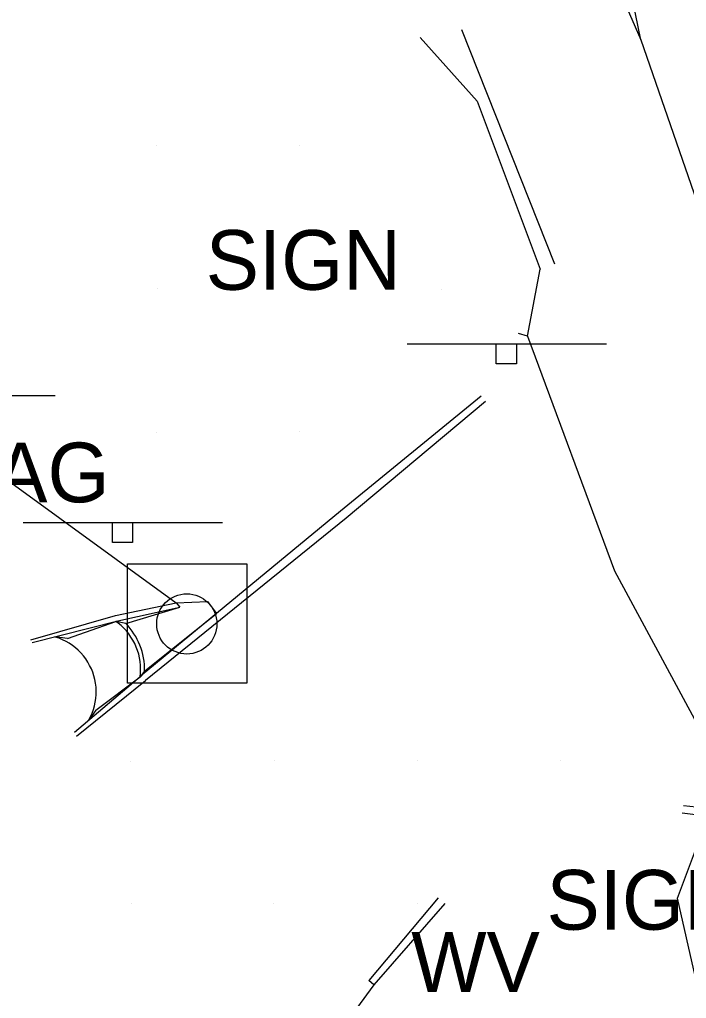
# Model space of a CAD drawing. Extents: x 1602514 to 1609837, y 863887 to 871157.
# Drawn here: x 1604808.5 to 1604878.4, y 866771.5 to 866874 of the extents above; entities that cross this region are included whole.
import ezdxf

# ---------------------------------------------------------------- set-up
doc = ezdxf.new("R2010")
doc.units = 0
for name, color, linetype in [('Roadway-Signs', 7, 'Continuous'), ('Survey-Centerline', 7, 'Continuous'), ('Survey-Curbs', 7, 'Continuous'), ('Survey-Edge of pavement', 7, 'Continuous'), ('Survey-Miscellaneous roadside', 7, 'Continuous'), ('Survey-Ridge Lines', 7, 'Continuous'), ('Survey-Shoulders', 7, 'Continuous'), ('Survey-Spot dirt', 7, 'Continuous'), ('Utility-Water', 7, 'Continuous')]:
    doc.layers.add(name, color=color, linetype=linetype)

msp = doc.modelspace()

# ---------------------------------------------------------------- linework, layer by layer
at = {"layer": 'Roadway-Signs'}
for p, q in [((1604849.12, 866840.02), (1604870.02, 866840.02)), ((1604849.12, 866840.02), (1604870.02, 866840.02)), ((1604858.47, 866837.92), (1604858.47, 866840.02)), ((1604858.47, 866837.92), (1604858.47, 866840.02)), ((1604859.52, 866840.02), (1604859.52, 866840.02)), ((1604859.52, 866840.02), (1604859.52, 866840.02)), ((1604860.57, 866840.02), (1604860.57, 866837.92)), ((1604860.57, 866840.02), (1604860.57, 866837.92)), ((1604860.57, 866837.92), (1604858.47, 866837.92)), ((1604860.57, 866837.92), (1604858.47, 866837.92)), ((1604791.37, 866834.63), (1604812.27, 866834.63)), ((1604791.37, 866834.63), (1604812.27, 866834.63)), ((1604808.91, 866821.33), (1604829.81, 866821.33)), ((1604808.91, 866821.33), (1604829.81, 866821.33)), ((1604818.26, 866819.23), (1604818.26, 866821.33)), ((1604818.26, 866819.23), (1604818.26, 866821.33)), ((1604819.31, 866821.33), (1604819.31, 866821.33)), ((1604819.31, 866821.33), (1604819.31, 866821.33)), ((1604820.36, 866821.33), (1604820.36, 866819.23)), ((1604820.36, 866821.33), (1604820.36, 866819.23)), ((1604820.36, 866819.23), (1604818.26, 866819.23)), ((1604820.36, 866819.23), (1604818.26, 866819.23))]:
    msp.add_line(p, q, dxfattribs=at)
at = {"layer": 'Survey-Centerline'}
msp.add_lwpolyline([(1604873.59, 866871.86), (1604870.26, 866888.2), (1604868.28, 866902.98), (1604861.37, 866899.9), (1604873.59, 866871.86)], dxfattribs=at)
msp.add_lwpolyline([(1604873.59, 866871.86), (1604870.26, 866888.2), (1604868.28, 866902.98), (1604861.37, 866899.9), (1604873.59, 866871.86)], dxfattribs=at)
at = {"layer": 'Survey-Curbs'}
for p, q in [((1604861.73, 866840.82), (1604860.81, 866841.1)), ((1604861.73, 866840.82), (1604860.81, 866841.1)), ((1604856.89, 866834.56), (1604842.14, 866822.52)), ((1604856.89, 866834.56), (1604842.14, 866822.52)), ((1604842.14, 866822.52), (1604821.39, 866805.36)), ((1604842.14, 866822.52), (1604821.39, 866805.36)), ((1604818.85, 866811.03), (1604825.31, 866812.46)), ((1604818.85, 866811.03), (1604825.31, 866812.46)), ((1604809.71, 866809.05), (1604818.59, 866811.58)), ((1604809.71, 866809.05), (1604818.59, 866811.58)), ((1604809.86, 866808.74), (1604818.85, 866811.03)), ((1604809.86, 866808.74), (1604818.85, 866811.03)), ((1604814.31, 866799.38), (1604821.39, 866805.36)), ((1604814.31, 866799.38), (1604821.39, 866805.36)), ((1604814.51, 866798.94), (1604821.73, 866804.77)), ((1604814.51, 866798.94), (1604821.73, 866804.77)), ((1604884.49, 866790.95), (1604878.07, 866791.65)), ((1604884.49, 866790.95), (1604878.07, 866791.65)), ((1604852.37, 866782.01), (1604845.13, 866773.36)), ((1604852.37, 866782.01), (1604845.13, 866773.36)), ((1604853.08, 866781.42), (1604845.65, 866772.91)), ((1604853.08, 866781.42), (1604845.65, 866772.91)), ((1604845.65, 866772.91), (1604845.13, 866773.36)), ((1604845.65, 866772.91), (1604845.13, 866773.36))]:
    msp.add_line(p, q, dxfattribs=at)
for points in [[(1604857.35, 866834), (1604842.76, 866821.76), (1604821.73, 866804.77)], [(1604857.35, 866834), (1604842.76, 866821.76), (1604821.73, 866804.77)], [(1604818.59, 866811.58), (1604824.93, 866812.89), (1604825.31, 866812.46)], [(1604818.59, 866811.58), (1604824.93, 866812.89), (1604825.31, 866812.46)], [(1604884.49, 866790.95), (1604884.32, 866790.1), (1604877.92, 866790.89)], [(1604884.49, 866790.95), (1604884.32, 866790.1), (1604877.92, 866790.89)]]:
    msp.add_lwpolyline(points, dxfattribs=at)
at = {"layer": 'Survey-Edge of pavement'}
for p, q in [((1604854.82, 866872.94), (1604864.57, 866848.39)), ((1604854.82, 866872.94), (1604864.57, 866848.39)), ((1604861.73, 866840.82), (1604863.05, 866847.84)), ((1604861.73, 866840.82), (1604863.05, 866847.84))]:
    msp.add_line(p, q, dxfattribs=at)
for points in [[(1604691.74, 866913.93), (1604754.93, 866864.89), (1604787.98, 866839.79), (1604824.93, 866812.89)], [(1604691.74, 866913.93), (1604754.93, 866864.89), (1604787.98, 866839.79), (1604824.93, 866812.89)], [(1604861.73, 866840.82), (1604870.85, 866816.25), (1604884.49, 866790.95)], [(1604861.73, 866840.82), (1604870.85, 866816.25), (1604884.49, 866790.95)], [(1604824.93, 866812.89), (1604828.23, 866813.03), (1604829.18, 866811.8)], [(1604824.93, 866812.89), (1604828.23, 866813.03), (1604829.18, 866811.8)], [(1604821.17, 866805.17), (1604821.21, 866805.56), (1604821.22, 866805.96), (1604821.21, 866806.35), (1604821.17, 866806.75), (1604821.11, 866807.14), (1604821.02, 866807.53), (1604820.9, 866807.91), (1604820.77, 866808.28), (1604820.6, 866808.64), (1604820.42, 866809), (1604820.21, 866809.33), (1604819.98, 866809.66), (1604819.73, 866809.97), (1604819.46, 866810.26), (1604819.17, 866810.53), (1604818.86, 866810.79), (1604818.62, 866810.97)], [(1604821.17, 866805.17), (1604821.21, 866805.56), (1604821.22, 866805.96), (1604821.21, 866806.35), (1604821.17, 866806.75), (1604821.11, 866807.14), (1604821.02, 866807.53), (1604820.9, 866807.91), (1604820.77, 866808.28), (1604820.6, 866808.64), (1604820.42, 866809), (1604820.21, 866809.33), (1604819.98, 866809.66), (1604819.73, 866809.97), (1604819.46, 866810.26), (1604819.17, 866810.53), (1604818.86, 866810.79), (1604818.62, 866810.97)], [(1604815.8, 866800.64), (1604815.98, 866801), (1604816.14, 866801.36), (1604816.28, 866801.74), (1604816.39, 866802.12), (1604816.47, 866802.51), (1604816.53, 866802.9), (1604816.56, 866803.3), (1604816.57, 866803.69), (1604816.55, 866804.09), (1604816.5, 866804.48), (1604816.43, 866804.87), (1604816.33, 866805.26), (1604816.2, 866805.64), (1604816.06, 866806.01), (1604815.88, 866806.36), (1604815.69, 866806.71), (1604815.47, 866807.04), (1604815.23, 866807.36), (1604814.97, 866807.66), (1604814.69, 866807.94), (1604814.4, 866808.21), (1604814.08, 866808.45), (1604813.75, 866808.67), (1604813.41, 866808.87), (1604813.05, 866809.05), (1604812.69, 866809.2), (1604812.31, 866809.33), (1604812.25, 866809.35)], [(1604815.8, 866800.64), (1604815.98, 866801), (1604816.14, 866801.36), (1604816.28, 866801.74), (1604816.39, 866802.12), (1604816.47, 866802.51), (1604816.53, 866802.9), (1604816.56, 866803.3), (1604816.57, 866803.69), (1604816.55, 866804.09), (1604816.5, 866804.48), (1604816.43, 866804.87), (1604816.33, 866805.26), (1604816.2, 866805.64), (1604816.06, 866806.01), (1604815.88, 866806.36), (1604815.69, 866806.71), (1604815.47, 866807.04), (1604815.23, 866807.36), (1604814.97, 866807.66), (1604814.69, 866807.94), (1604814.4, 866808.21), (1604814.08, 866808.45), (1604813.75, 866808.67), (1604813.41, 866808.87), (1604813.05, 866809.05), (1604812.69, 866809.2), (1604812.31, 866809.33), (1604812.25, 866809.35)], [(1604845.65, 866772.91), (1604822.6, 866741.47), (1604796.09, 866704.84), (1604775.38, 866676.02), (1604745.42, 866684.38), (1604717.27, 866690.11)], [(1604845.65, 866772.91), (1604822.6, 866741.47), (1604796.09, 866704.84), (1604775.38, 866676.02), (1604745.42, 866684.38), (1604717.27, 866690.11)]]:
    msp.add_lwpolyline(points, dxfattribs=at)
at = {"layer": 'Survey-Miscellaneous roadside'}
for p, q in [((1604819.86, 866804.5), (1604819.86, 866817)), ((1604819.86, 866817), (1604832.36, 866817)), ((1604819.86, 866804.5), (1604819.86, 866817)), ((1604819.86, 866817), (1604832.36, 866817)), ((1604832.36, 866817), (1604832.36, 866804.5)), ((1604832.36, 866817), (1604832.36, 866804.5)), ((1604832.36, 866804.5), (1604819.86, 866804.5)), ((1604832.36, 866804.5), (1604819.86, 866804.5))]:
    msp.add_line(p, q, dxfattribs=at)
msp.add_circle((1604826.05, 866810.7), 3.15, dxfattribs=at)
msp.add_circle((1604826.05, 866810.7), 3.15, dxfattribs=at)
at = {"layer": 'Survey-Ridge Lines'}
for p, q in [((1604873.59, 866871.86), (1604882.54, 866845.98)), ((1604873.59, 866871.86), (1604882.54, 866845.98)), ((1604819.66, 866810.75), (1604825.31, 866812.46)), ((1604819.66, 866810.75), (1604825.31, 866812.46)), ((1604821.64, 866805.77), (1604829.18, 866811.8)), ((1604821.64, 866805.77), (1604829.18, 866811.8)), ((1604813.57, 866809.16), (1604818.62, 866810.97)), ((1604813.57, 866809.16), (1604818.62, 866810.97)), ((1604819.66, 866810.75), (1604818.62, 866810.97)), ((1604819.66, 866810.75), (1604818.62, 866810.97)), ((1604813.57, 866809.16), (1604812.25, 866809.35)), ((1604813.57, 866809.16), (1604812.25, 866809.35)), ((1604816.52, 866801.66), (1604821.17, 866805.17)), ((1604816.52, 866801.66), (1604821.17, 866805.17)), ((1604821.64, 866805.77), (1604821.17, 866805.17)), ((1604821.64, 866805.77), (1604821.17, 866805.17)), ((1604816.52, 866801.66), (1604815.8, 866800.64)), ((1604816.52, 866801.66), (1604815.8, 866800.64))]:
    msp.add_line(p, q, dxfattribs=at)
msp.add_lwpolyline([(1604879.66, 866787.86), (1604887.13, 866786.19), (1604892.43, 866779.73), (1604897.93, 866766.89), (1604897.57, 866761.56), (1604891.37, 866761.46), (1604880.26, 866769.53), (1604877.43, 866782)], close=True, dxfattribs=at)
msp.add_lwpolyline([(1604879.66, 866787.86), (1604887.13, 866786.19), (1604892.43, 866779.73), (1604897.93, 866766.89), (1604897.57, 866761.56), (1604891.37, 866761.46), (1604880.26, 866769.53), (1604877.43, 866782)], close=True, dxfattribs=at)
msp.add_arc((1604814.68, 866805.89), 6.96, 359.0578, 44.2786, dxfattribs=at)
msp.add_arc((1604814.68, 866805.89), 6.96, 359.0578, 44.2786, dxfattribs=at)
at = {"layer": 'Survey-Shoulders'}
msp.add_lwpolyline([(1604850.49, 866872.1), (1604856.45, 866865.44), (1604863.05, 866847.84)], dxfattribs=at)
msp.add_lwpolyline([(1604850.49, 866872.1), (1604856.45, 866865.44), (1604863.05, 866847.84)], dxfattribs=at)
at = {"layer": 'Survey-Spot dirt'}
for p, q in [((1604822.91, 866860.83), (1604822.91, 866860.83)), ((1604822.91, 866860.83), (1604822.91, 866860.83)), ((1604837.91, 866860.79), (1604837.91, 866860.79)), ((1604837.91, 866860.79), (1604837.91, 866860.79)), ((1604822.95, 866845.8), (1604822.95, 866845.8)), ((1604822.95, 866845.8), (1604822.95, 866845.8)), ((1604837.95, 866845.82), (1604837.95, 866845.82)), ((1604837.95, 866845.82), (1604837.95, 866845.82)), ((1604852.68, 866845.69), (1604852.68, 866845.69)), ((1604852.68, 866845.69), (1604852.68, 866845.69)), ((1604822.93, 866830.76), (1604822.93, 866830.76)), ((1604822.93, 866830.76), (1604822.93, 866830.76)), ((1604837.9, 866830.82), (1604837.9, 866830.82)), ((1604837.9, 866830.82), (1604837.9, 866830.82)), ((1604820.31, 866811.37), (1604820.31, 866811.37)), ((1604820.31, 866811.37), (1604820.31, 866811.37)), ((1604820.2, 866796.31), (1604820.2, 866796.31)), ((1604820.2, 866796.31), (1604820.2, 866796.31)), ((1604835.21, 866796.37), (1604835.21, 866796.37)), ((1604835.21, 866796.37), (1604835.21, 866796.37)), ((1604850.18, 866796.45), (1604850.18, 866796.45)), ((1604850.18, 866796.45), (1604850.18, 866796.45)), ((1604865.2, 866796.43), (1604865.2, 866796.43)), ((1604865.2, 866796.43), (1604865.2, 866796.43)), ((1604865.15, 866781.54), (1604865.15, 866781.54)), ((1604865.15, 866781.54), (1604865.15, 866781.54)), ((1604820.26, 866781.4), (1604820.26, 866781.4)), ((1604820.26, 866781.4), (1604820.26, 866781.4)), ((1604835.16, 866781.45), (1604835.16, 866781.45)), ((1604835.16, 866781.45), (1604835.16, 866781.45)), ((1604850.2, 866781.41), (1604850.2, 866781.41)), ((1604850.2, 866781.41), (1604850.2, 866781.41))]:
    msp.add_line(p, q, dxfattribs=at)

# ---------------------------------------------------------------- texts
at = {"layer": 'Roadway-Signs'}
for p in [(1604828.04, 866845.68), (1604828.04, 866845.68), (1604863.73, 866778.69), (1604863.73, 866778.69)]:
    msp.add_text('SIGN', height=6.25, dxfattribs=at).set_placement(p)
at = {"layer": 'Survey-Miscellaneous roadside'}
msp.add_text('FLAG', height=6.25, dxfattribs=at).set_placement((1604796.14, 866823.43))
msp.add_text('FLAG', height=6.25, dxfattribs=at).set_placement((1604796.14, 866823.43))
at = {"layer": 'Utility-Water'}
msp.add_text('WV', height=6.251, dxfattribs=at).set_placement((1604849.56, 866772.18))
msp.add_text('WV', height=6.251, dxfattribs=at).set_placement((1604849.56, 866772.18))

doc.saveas('drawing.dxf')
